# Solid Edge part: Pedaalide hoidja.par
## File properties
Author: Türk
Template: iso part.par
Last saved by: Türk
Revision: 3
Application: Solid Edge
Accuracy: 0,990
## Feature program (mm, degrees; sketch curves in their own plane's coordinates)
base feature "unnamed BaseFeature 1"
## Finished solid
Body 1: solid body, 31 faces, 73 edges, 42 vertices.
  Faces by surface: plane 23, cylinder 8
  Edges by curve: line 57, circle 16
Bounding box of the edges (mm): 180.377 x 120.566 x 62.500, from (336.2071, 927.4999, -65) to (516.584, 1048.066, -2.5001).
Cylindrical faces by radius (mm): R10 x4, R22.4999 x4
Planar faces by outward normal: +z 1, -z 2, oblique 20
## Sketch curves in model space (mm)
circle centre (324.3116, 967.4999, -25) radius 10
line (324.3116, 967.4999, -55) -> (324.3116, 989.9999, -55)
line (324.3116, 989.9999, -55) -> (324.3116, 989.9999, -25)
arc centre (324.3116, 967.4999, -25) radius 22.5 from (324.3116, 944.9999, -25) through (324.3116, 968.1667, -2.5099) to (324.3116, 989.9999, -25)
line (324.3116, 944.9999, -25) -> (324.3116, 944.9999, -55)
line (324.3116, 944.9999, -55) -> (324.3116, 967.4999, -55)
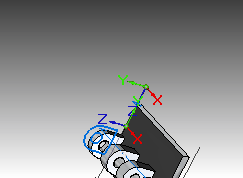
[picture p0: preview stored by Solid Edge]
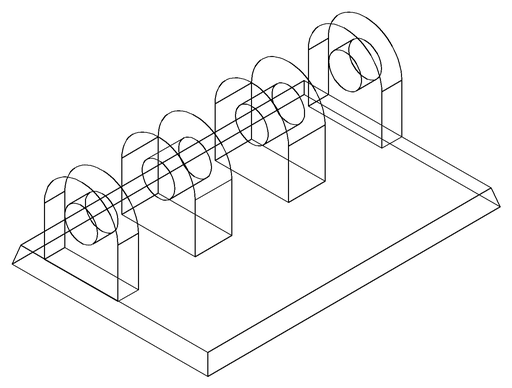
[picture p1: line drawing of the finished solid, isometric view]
